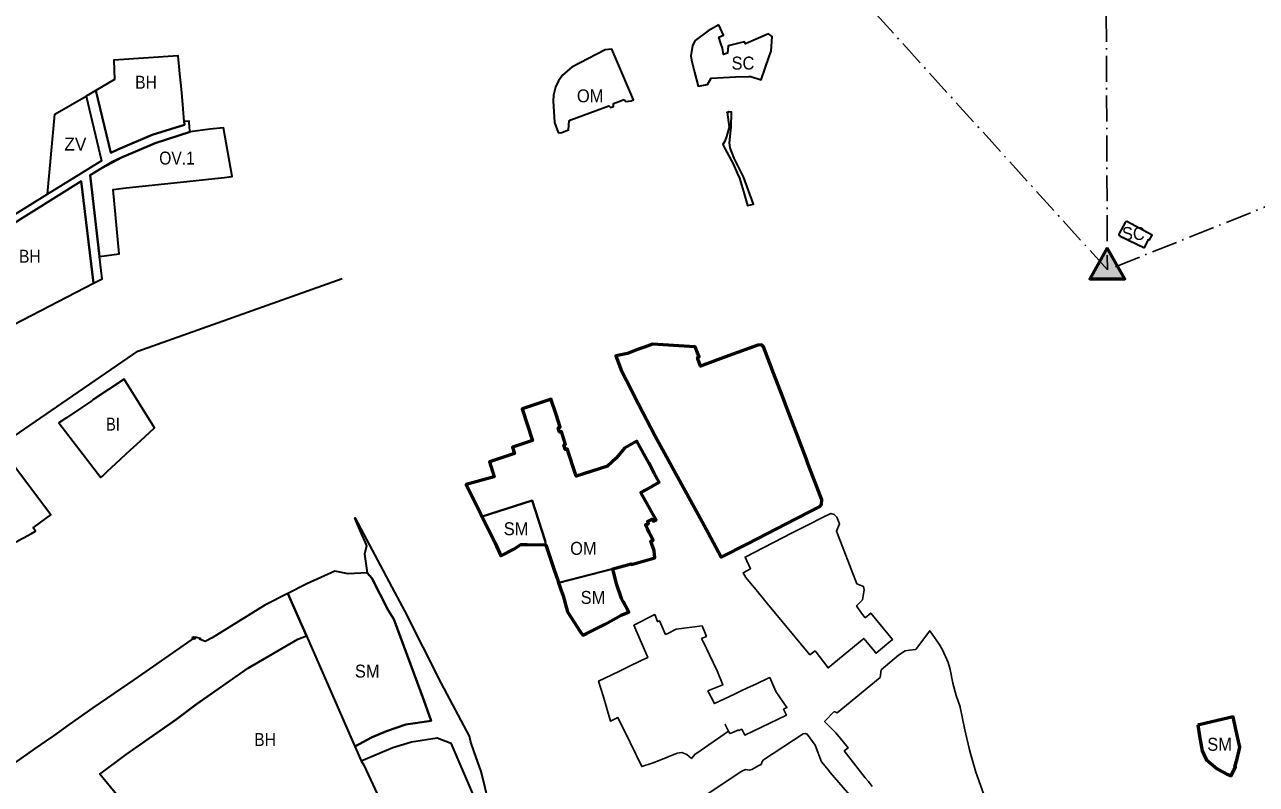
# Model space of a CAD drawing. Extents: x -650276 to -642489, y -1074311 to -1066658.
# Drawn here: x -648072 to -646929, y -1071077 to -1070373 of the extents above; entities that cross this region are included whole.
import ezdxf

# ---------------------------------------------------------------- set-up
doc = ezdxf.new("R2010")
doc.units = 0
doc.header["$LTSCALE"] = 4.8
doc.header["$PDMODE"] = 32
doc.header["$PDSIZE"] = 2.4
doc.linetypes.add('DOT_DASHED', pattern=[7.7, 5, -1.2, 0.3, -1.2])
for name, color, linetype, lineweight in [('1', 7, 'Continuous', 35), ('11', 7, 'Continuous', 35), ('12', 7, 'Continuous', 35), ('15', 7, 'Continuous', 35), ('17', 7, 'Continuous', 35), ('18', 7, 'Continuous', 35), ('2', 7, 'Continuous', 35), ('40', 7, 'Continuous', 35), ('54', 7, 'Continuous', 35), ('55', 7, 'Continuous', 53), ('60', 7, 'Continuous', 53), ('61', 7, 'Continuous', 25)]:
    doc.layers.add(name, color=color, linetype=linetype, lineweight=lineweight)
doc.layers.add('62', color=7, linetype='Continuous')

msp = doc.modelspace()

# ---------------------------------------------------------------- hatches: boundary and pattern name
at = {"layer": '55'}
msp.add_hatch(color=256, dxfattribs=at).paths.add_polyline_path([(-647067.857, -1070579.969), (-647083.808, -1070608.615), (-647051.424, -1070608.615)])

# ---------------------------------------------------------------- linework, layer by layer
at = {"layer": '1'}
for points in [[(-647991.539, -1070492.016), (-647985.19, -1070488.804), (-647953.251, -1070475.276), (-647923.247, -1070465.749), (-647923.53, -1070462.75), (-647924.63, -1070451.09), (-647925.5, -1070439.63), (-647926.53, -1070429.76), (-647927.67, -1070418.74), (-647929.24, -1070401.97), (-647988.86, -1070405.95), (-647988.11, -1070423.93), (-648005.668, -1070434.145)], [(-648098.637, -1070659.682), (-648007.838, -1070612.851), (-648019, -1070518), (-648135.47, -1070590.61), (-648105.98, -1070645.91)], [(-648001.922, -1071067.83), (-647977.41, -1071049.74), (-647930.7, -1071017.18), (-647911.838, -1071002.919), (-647864.03, -1070969.3), (-647864.03, -1070969.3), (-647818.33, -1070942.91), (-647810.243, -1070939.825), (-647759.52, -1071055.67), (-647757.19, -1071059.66), (-647742.64, -1071090.72), (-647726.74, -1071122.48), (-647742.35, -1071129.43), (-647775.982, -1071148.001), (-647775.982, -1071148.001), (-647875.939, -1071221.104)]]:
    msp.add_lwpolyline(points, close=True, dxfattribs=at)
at = {"layer": '11'}
msp.add_lwpolyline([(-647927.14, -1070519), (-647889.27, -1070514.92), (-647886.09, -1070514.58), (-647879.89, -1070513.91), (-647879.16, -1070513.83), (-647887.08, -1070468.54), (-647899.87, -1070470.04), (-647917.98, -1070472.47), (-647950.48, -1070482.79), (-647981.81, -1070496.06), (-647990.295, -1070500.352), (-647999.756, -1070505.655), (-648010.831, -1070512.588), (-648002, -1070588), (-647984.03, -1070585.46), (-647989.5, -1070525.73), (-647977.41, -1070524.43)], close=True, dxfattribs=at)
at = {"layer": '12'}
msp.add_lwpolyline([(-647515.73, -1070442.32), (-647514.23, -1070444.18), (-647509.22, -1070443.62), (-647506.95, -1070442.71), (-647522.54, -1070406.51), (-647527.1, -1070395.72), (-647533.1, -1070396.26), (-647564.01, -1070412.59), (-647572.37, -1070419.41), (-647576.48, -1070425.09), (-647579.22, -1070431.05), (-647581.04, -1070438.4), (-647581.54, -1070443.7), (-647580.1, -1070463.69), (-647576.92, -1070473), (-647574.28, -1070473.46), (-647567.32, -1070470.66), (-647566.55, -1070462.22), (-647565.11, -1070461.12), (-647529.74, -1070448.27), (-647528.28, -1070449.87), (-647525.54, -1070448.89), (-647525.45, -1070446.21)], close=True, dxfattribs=at)
msp.add_lwpolyline([(-647515.73, -1070442.32), (-647514.23, -1070444.18), (-647509.22, -1070443.62), (-647506.95, -1070442.71), (-647522.54, -1070406.51), (-647527.1, -1070395.72), (-647533.1, -1070396.26), (-647564.01, -1070412.59), (-647572.37, -1070419.41), (-647576.48, -1070425.09), (-647579.22, -1070431.05), (-647581.04, -1070438.4), (-647581.54, -1070443.7), (-647580.1, -1070463.69), (-647576.92, -1070473), (-647574.28, -1070473.46), (-647567.32, -1070470.66), (-647566.55, -1070462.22), (-647565.11, -1070461.12), (-647529.74, -1070448.27), (-647528.28, -1070449.87), (-647525.54, -1070448.89), (-647525.45, -1070446.21)], close=True, dxfattribs=at)
msp.add_lwpolyline([(-647515.73, -1070442.32), (-647514.23, -1070444.18), (-647509.22, -1070443.62), (-647506.95, -1070442.71), (-647522.54, -1070406.51), (-647527.1, -1070395.72), (-647533.1, -1070396.26), (-647564.01, -1070412.59), (-647572.37, -1070419.41), (-647576.48, -1070425.09), (-647579.22, -1070431.05), (-647581.04, -1070438.4), (-647581.54, -1070443.7), (-647580.1, -1070463.69), (-647576.92, -1070473), (-647574.28, -1070473.46), (-647567.32, -1070470.66), (-647566.55, -1070462.22), (-647565.11, -1070461.12), (-647529.74, -1070448.27), (-647528.28, -1070449.87), (-647525.54, -1070448.89), (-647525.45, -1070446.21)], close=True, dxfattribs=at)
for points in [[(-647569.92, -1070762.24), (-647573.88, -1070750.25), (-647575.58, -1070750.83), (-647576.81, -1070746.86), (-647575.09, -1070746.33), (-647578.79, -1070734.33), (-647583.38, -1070720.9), (-647583.22, -1070720.2), (-647593.6, -1070723.68), (-647610.33, -1070729.28), (-647600.53, -1070758.65), (-647619.2, -1070764.85), (-647617.36, -1070770.69)], [(-647636.12, -1070792.13), (-647654.89, -1070797.23), (-647662.26, -1070799.23), (-647650.908, -1070822.34), (-647647.405, -1070829.08), (-647609.58, -1070817.06), (-647600.8, -1070814.27), (-647588.89, -1070851.67), (-647588.4, -1070855.25), (-647584.6, -1070866.3), (-647580.22, -1070879.3), (-647578.703, -1070883.851), (-647578.703, -1070883.851), (-647576.469, -1070890.564), (-647526.13, -1070877.41), (-647509.1, -1070872.96), (-647508.96, -1070873.41), (-647487.16, -1070867.32), (-647487.91, -1070860.91), (-647490.92, -1070851.82), (-647488.8, -1070851.12), (-647494.1, -1070840.58), (-647495.93, -1070836.86), (-647493.16, -1070835.5), (-647494.03, -1070833.64), (-647489.55, -1070831.53), (-647488.75, -1070833.37), (-647485.9, -1070832), (-647500.07, -1070806.87), (-647500.07, -1070806.87), (-647483.16, -1070797.07), (-647492.81, -1070779.18), (-647492.81, -1070779.18), (-647497.227, -1070771.165), (-647503.76, -1070759.31), (-647514.49, -1070764.93), (-647517.61, -1070767.89), (-647523.07, -1070774.86), (-647531.05, -1070782.23), (-647560.06, -1070791.72), (-647566.26, -1070773.148)], [(-647570.27, -1070766.86), (-647571.63, -1070762.82), (-647569.92, -1070762.24)], [(-647566.26, -1070773.148), (-647568.55, -1070766.29), (-647570.27, -1070766.86)], [(-647617.36, -1070770.69), (-647619.12, -1070771.28), (-647640.66, -1070778.47), (-647636.12, -1070792.13)]]:
    msp.add_lwpolyline(points, dxfattribs=at)
at = {"layer": '15'}
for points in [[(-648007.838, -1070612.851), (-647999.588, -1070608.596), (-648002, -1070588), (-648010.831, -1070512.588), (-647999.756, -1070505.655), (-647981.81, -1070496.06), (-647950.48, -1070482.79), (-647917.98, -1070472.47), (-647918.54, -1070468.61), (-647918.95, -1070462.36), (-647923.53, -1070462.75), (-647923.247, -1070465.749), (-647953.251, -1070475.276), (-647985.19, -1070488.804), (-647991.539, -1070492.016), (-648005.668, -1070434.145), (-648014.63, -1070439.36), (-648000.442, -1070499.336), (-648019.789, -1070511.293), (-648050.38, -1070530.2), (-648122.57, -1070575), (-648137.78, -1070586.25), (-648135.47, -1070590.61), (-648019, -1070518)], [(-647404.96, -1070527.57), (-647401.35, -1070540.59), (-647395.75, -1070539.47), (-647404.879, -1070514.114), (-647413.552, -1070496.671), (-647417.297, -1070487.185), (-647418.038, -1070482.516), (-647417.482, -1070476.846), (-647416.37, -1070468.064), (-647416.148, -1070454.055), (-647418.49, -1070453.76), (-647420.13, -1070454.78), (-647420.22, -1070454.02), (-647418.41, -1070468.21), (-647420.74, -1070476.57), (-647422.285, -1070480.931), (-647424.226, -1070484.029), (-647422.19, -1070487.75), (-647414.6, -1070502.16), (-647410.86, -1070510.68), (-647408.82, -1070515.49)]]:
    msp.add_lwpolyline(points, close=True, dxfattribs=at)
for points in [[(-647659.01, -1071032.66), (-647685.1, -1070983.93), (-647719.06, -1070916.45), (-647728.35, -1070899.11), (-647764.84, -1070830.47), (-647765.72, -1070830.64)], [(-647765.72, -1070830.64), (-647759.08, -1070845.74), (-647755.87, -1070853.02), (-647754.6, -1070856.11), (-647756.45, -1070863.95), (-647753.81, -1070881.3)], [(-647753.81, -1070881.3), (-647749.75, -1070886.1), (-647734.48, -1070915.94), (-647729.27, -1070924.35), (-647701.45, -1070999.4)], [(-647701.45, -1070999.4), (-647694.54, -1071018.549), (-647718, -1071022), (-647736, -1071028), (-647750, -1071034), (-647765.408, -1071042.223), (-647759.52, -1071055.67), (-647730.17, -1071043.21), (-647712.74, -1071037.99), (-647688.9, -1071034.18), (-647676.96, -1071039.014)], [(-647676.96, -1071039.014), (-647676.9, -1071039.03), (-647676.45, -1071039.22), (-647656.443, -1071085.369), (-647658.55, -1071097.02), (-647669.02, -1071102.33), (-647667.35, -1071106.38), (-647655.47, -1071100.98), (-647640.727, -1071095.819)], [(-647640.727, -1071095.819), (-647648.106, -1071065.551), (-647654.747, -1071047.095), (-647657.699, -1071038.232), (-647659.01, -1071032.66)]]:
    msp.add_lwpolyline(points, dxfattribs=at)
at = {"layer": '17'}
for points in [[(-647427.8, -1070373.32), (-647437.76, -1070378.66), (-647449.69, -1070387.83), (-647452.17, -1070392.38), (-647453.71, -1070401.81), (-647453.35, -1070406.09), (-647450.51, -1070416.96), (-647446.93, -1070429.99), (-647438.45, -1070428.47), (-647434.85, -1070422.64), (-647423.38, -1070421.87), (-647412.51, -1070421.5), (-647400.41, -1070421.08), (-647398.21, -1070421.15), (-647388.6, -1070424.24), (-647381.11, -1070402.45), (-647379.3, -1070397.57), (-647378.49, -1070383.91), (-647381.65, -1070381.45), (-647400.22, -1070389.64), (-647403.27, -1070390.91), (-647404, -1070388.84), (-647409.36, -1070390.24), (-647419.08, -1070392.52), (-647419.68, -1070399.59), (-647423.58, -1070400.59), (-647424.54, -1070394.78), (-647425.99, -1070390.47), (-647427.96, -1070384.64), (-647423.57, -1070382.64)], [(-647033.01, -1070579.83), (-647029.44, -1070572.13), (-647028.52, -1070572.63), (-647026.14, -1070568.26), (-647049.52, -1070555.64), (-647050.37, -1070555.74), (-647051.14, -1070556.59), (-647052.77, -1070559.7), (-647056.79, -1070567.41), (-647056.8, -1070568.32), (-647055.79, -1070569.07)]]:
    msp.add_lwpolyline(points, close=True, dxfattribs=at)
at = {"layer": '18'}
for points in [[(-647588.4, -1070855.25), (-647588.89, -1070851.67), (-647600.8, -1070814.27), (-647609.58, -1070817.06), (-647647.405, -1070829.08)], [(-647647.405, -1070829.08), (-647635.11, -1070853.786), (-647629.92, -1070865.35), (-647618.01, -1070859.42), (-647611.3, -1070854.9), (-647605.64, -1070854.99), (-647588.4, -1070855.25)], [(-647511.37, -1070917.79), (-647516.66, -1070907.8), (-647518.12, -1070905.05), (-647522.74, -1070891.48), (-647526.13, -1070877.41), (-647576.469, -1070890.564)], [(-647576.469, -1070890.564), (-647576.43, -1070890.68), (-647575.35, -1070893.91), (-647574.09, -1070897.7), (-647572.32, -1070902.72), (-647568.2, -1070917.54), (-647556.52, -1070935.59), (-647553.94, -1070939.11)], [(-647553.94, -1070939.11), (-647553.94, -1070939.11), (-647550.59, -1070937.45), (-647533.31, -1070928.79), (-647518.35, -1070920.62)], [(-647518.35, -1070920.62), (-647514.7, -1070918.79), (-647511.37, -1070917.79)]]:
    msp.add_lwpolyline(points, dxfattribs=at)
for points in [[(-647736, -1071028), (-647718, -1071022), (-647694.54, -1071018.549), (-647701.45, -1070999.4), (-647729.27, -1070924.35), (-647734.48, -1070915.94), (-647749.75, -1070886.1), (-647753.81, -1070881.3), (-647771.47, -1070882.27), (-647783.95, -1070879.58), (-647809.74, -1070891.31), (-647827.527, -1070900.351), (-647810.243, -1070939.825), (-647765.408, -1071042.223), (-647750, -1071034)], [(-646983.66, -1071022.3), (-646982.08, -1071032.76), (-646979.75, -1071046.19), (-646976.03, -1071054.29), (-646965.69, -1071063.05), (-646956.66, -1071067.91), (-646952.75, -1071069.62), (-646948.83, -1071061.12), (-646949.48, -1071060.79), (-646947.41, -1071054.95), (-646945.38, -1071045.82), (-646944.88, -1071042.78), (-646948.89, -1071024.84), (-646949.39, -1071021.83), (-646951.06, -1071014.78), (-646955.09, -1071015.67)]]:
    msp.add_lwpolyline(points, close=True, dxfattribs=at)
at = {"layer": '2'}
for points in [[(-648032.601, -1070737.472), (-648039.82, -1070742.33), (-648000.85, -1070792.88), (-647999.06, -1070791.2), (-647994.63, -1070787.05), (-647994.63, -1070787.05), (-647982.89, -1070776.05), (-647976.97, -1070770.51), (-647964.21, -1070758.77), (-647951.11, -1070746.78), (-647979.17, -1070701.65), (-648008.28, -1070720.96), (-648009.29, -1070721.79), (-648019.49, -1070728.65)], [(-648114.77, -1070788.08), (-648125.2, -1070794.79), (-648083.65, -1070854.89), (-648076.73, -1070851.07), (-648074.41, -1070849.79), (-648072.59, -1070848.79), (-648065.35, -1070844.8), (-648061.52, -1070842.68), (-648063.76, -1070839.49), (-648056.61, -1070834.26), (-648047.17, -1070827.35), (-648089.27, -1070771.57), (-648104.78, -1070781.65)]]:
    msp.add_lwpolyline(points, close=True, dxfattribs=at)
msp.add_lwpolyline([(-647875.939, -1071221.104), (-648001.922, -1071067.83), (-647977.41, -1071049.74), (-647930.96, -1071017.383), (-647912.11, -1071003.11), (-647864.29, -1070969.503), (-647818.33, -1070942.91), (-647810.243, -1070939.825), (-647827.527, -1070900.351), (-647848.89, -1070911.21), (-647897.76, -1070941.62), (-647904.13, -1070944.78), (-647909.42, -1070942.63), (-647908.63, -1070942.1), (-647913.45, -1070940.79), (-647934.9, -1070955.87), (-647952.01, -1070967.82), (-647970.19, -1070980.45), (-647988.81, -1070993.27), (-648008.34, -1071006.32), (-648030.24, -1071021.91), (-648044.82, -1071032.25), (-648051.48, -1071036.97), (-648062.53, -1071044.59), (-648085.73, -1071060.92)], dxfattribs=at)
msp.add_point((-647914.73, -1070941.682), dxfattribs=at)
at = {"layer": '40'}
msp.add_lwpolyline([(-648014.63, -1070439.36), (-648000.442, -1070499.336), (-648050.38, -1070530.2), (-648043.43, -1070456.12)], close=True, dxfattribs=at)
at = {"layer": '54'}
msp.add_lwpolyline([(-648756.915, -1070932.76), (-648403.845, -1070737.419), (-648368.964, -1070716.905), (-648263.103, -1070807.79), (-648213.358, -1070823.563), (-648181.392, -1070823.076), (-647966.625, -1070675.686), (-647777.125, -1070608.309)], dxfattribs=at)
at = {"layer": '55', "linetype": 'DOT_DASHED', "lineweight": 25}
for p, q in [((-647072.859, -1069440.93), (-647067.564, -1070600.224)), ((-647067.564, -1070600.224), (-647577.112, -1070037.236)), ((-647060.176, -1070597.455), (-645765.418, -1070080.935))]:
    msp.add_line(p, q, dxfattribs=at)
at = {"layer": '55'}
msp.add_lwpolyline([(-647067.857, -1070579.969), (-647083.808, -1070608.615), (-647051.424, -1070608.615)], close=True, dxfattribs=at)
at = {"layer": '60'}
for points in [[(-647365.48, -1070835.85), (-647334.27, -1070819.86), (-647332.51, -1070817.97), (-647332.25, -1070813.72), (-647345.18, -1070779.89), (-647346.96, -1070775.41), (-647365.94, -1070725.08), (-647367.67, -1070720.73), (-647377.04, -1070696.22), (-647386.39, -1070671.74), (-647388.31, -1070669.95), (-647391.74, -1070670.16), (-647418.28, -1070679.89), (-647444.78, -1070689.6), (-647447.31, -1070682.72), (-647447.76, -1070681.5), (-647446.22, -1070680.91), (-647447.58, -1070677.36), (-647449.69, -1070671.81), (-647455.17, -1070671.48), (-647489.21, -1070669.41), (-647496.64, -1070671.93), (-647503.3, -1070674.3), (-647512.51, -1070677.98), (-647523.27, -1070680.11), (-647518.19, -1070693.93), (-647513.59, -1070702.8), (-647502.59, -1070724.13), (-647486.84, -1070754.54), (-647464.3, -1070795.6), (-647448.84, -1070823.79), (-647437.79, -1070844.12), (-647425.58, -1070866.7), (-647401.15, -1070854.25)], [(-647588.4, -1070855.25), (-647584.6, -1070866.3), (-647580.22, -1070879.3), (-647577.59, -1070887.19), (-647576.43, -1070890.68), (-647575.35, -1070893.91), (-647574.09, -1070897.7), (-647572.32, -1070902.72), (-647568.2, -1070917.54), (-647556.52, -1070935.59), (-647553.94, -1070939.11), (-647550.59, -1070937.45), (-647533.31, -1070928.79), (-647518.35, -1070920.62), (-647511.37, -1070917.79), (-647516.66, -1070907.8), (-647518.12, -1070905.05), (-647522.74, -1070891.48), (-647526.13, -1070877.41), (-647509.1, -1070872.96), (-647508.96, -1070873.41), (-647487.16, -1070867.32), (-647487.91, -1070860.91), (-647490.92, -1070851.82), (-647488.8, -1070851.12), (-647491.19, -1070846.49), (-647492.48, -1070843.88), (-647494.1, -1070840.58), (-647495.93, -1070836.86), (-647493.16, -1070835.5), (-647494.03, -1070833.64), (-647489.55, -1070831.53), (-647488.75, -1070833.37), (-647485.9, -1070832), (-647500.07, -1070806.87), (-647500.07, -1070806.87), (-647494.88, -1070803.86), (-647483.16, -1070797.07), (-647487.67, -1070788.86), (-647492.81, -1070779.18), (-647503.76, -1070759.31), (-647515.216, -1070765.619), (-647523.07, -1070774.86), (-647531.05, -1070782.23), (-647560.06, -1070791.72), (-647568.55, -1070766.29), (-647570.27, -1070766.86), (-647571.63, -1070762.82), (-647569.92, -1070762.24), (-647573.88, -1070750.25), (-647575.58, -1070750.83), (-647576.81, -1070746.86), (-647575.09, -1070746.33), (-647578.79, -1070734.33), (-647583.38, -1070720.9), (-647583.22, -1070720.2), (-647593.6, -1070723.68), (-647610.33, -1070729.28), (-647600.53, -1070758.65), (-647619.2, -1070764.85), (-647617.36, -1070770.69), (-647640.66, -1070778.47), (-647636.12, -1070792.13), (-647662.26, -1070799.23), (-647635.11, -1070853.786), (-647629.92, -1070865.35), (-647618.01, -1070859.42), (-647611.3, -1070854.9), (-647605.64, -1070854.99)], [(-646983.66, -1071022.3), (-646982.08, -1071032.76), (-646979.75, -1071046.19), (-646976.03, -1071054.29), (-646965.69, -1071063.05), (-646956.66, -1071067.91), (-646952.75, -1071069.62), (-646948.83, -1071061.12), (-646949.48, -1071060.79), (-646947.41, -1071054.95), (-646945.38, -1071045.82), (-646944.88, -1071042.78), (-646948.89, -1071024.84), (-646949.39, -1071021.83), (-646951.06, -1071014.78), (-646955.09, -1071015.67), (-646982.41, -1071022.23)]]:
    msp.add_lwpolyline(points, close=True, dxfattribs=at)
at = {"layer": '61'}
for points in [[(-647299.98, -1070891.49), (-647318.68, -1070842.72), (-647316.06, -1070835.75), (-647318.44, -1070829.76), (-647321.01, -1070827.14), (-647324.15, -1070826.29), (-647331.02, -1070829.74), (-647345.71, -1070837.13), (-647359.71, -1070844.27), (-647403.51, -1070866.6), (-647398.52, -1070877.49), (-647405.34, -1070881.23), (-647402.82, -1070885.66), (-647396.9, -1070892.8), (-647394.88, -1070895.23), (-647382.57, -1070910.05), (-647343.34, -1070957.27), (-647338.57, -1070953.63), (-647326.51, -1070969.42), (-647293.51, -1070942.01), (-647290.28, -1070945.89), (-647283.54, -1070954.02), (-647282.46, -1070955.31), (-647281.97, -1070955.9), (-647271.95, -1070947.47), (-647266.79, -1070942.95), (-647286.92, -1070918.59), (-647292.14, -1070922.88), (-647295.69, -1070918.55), (-647300.07, -1070911.99), (-647294.73, -1070906.32), (-647293.09, -1070897.18), (-647293.7, -1070893.99)], [(-647466.48, -1071048.33), (-647483.08, -1071055.41), (-647489.7, -1071057.66), (-647499.39, -1071060.95), (-647510.18, -1071038.65), (-647521.36, -1071015.52), (-647528.27, -1071018.94), (-647535.19, -1070995.23), (-647539.38, -1070981.6), (-647520.58, -1070972.61), (-647517.43, -1070971.1), (-647511.96, -1070968.48), (-647499.8, -1070962.67), (-647493.79, -1070959.8), (-647493.71, -1070959.89), (-647506.58, -1070929.86), (-647487.33, -1070919.95), (-647484.78, -1070926.54), (-647483.02, -1070925.66), (-647477.21, -1070938.44), (-647475.82, -1070937.77), (-647467.47, -1070933.53), (-647443.36, -1070930.41), (-647439.33, -1070940.28), (-647443.84, -1070942.26), (-647442.33, -1070945.38), (-647441.9, -1070946.28), (-647436.58, -1070957.29), (-647429.44, -1070972.06), (-647424.16, -1070985.19), (-647438.05, -1070990.74), (-647431.74, -1071002.56), (-647413.35, -1070993.67), (-647410.26, -1070992.23), (-647407.22, -1070990.81), (-647401.93, -1070988.34), (-647392.83, -1070984.14), (-647382.05, -1070979.01), (-647380.69, -1070978.37), (-647374.95, -1070991.15), (-647364.66, -1071006.25), (-647367.88, -1071007.78), (-647365.21, -1071013.19), (-647403.85, -1071031.66), (-647406.65, -1071026.24), (-647409.36, -1071027.52), (-647409.68, -1071026.85), (-647411.52, -1071027.64), (-647415.84, -1071029.49), (-647417.76, -1071030.31), (-647418.88, -1071028.01), (-647421.89, -1071021.82), (-647418.88, -1071028.01), (-647448.32, -1071048.39), (-647449.88, -1071049.31), (-647453.32, -1071053.37), (-647457.4, -1071049.84), (-647462.03, -1071047.83)]]:
    msp.add_lwpolyline(points, close=True, dxfattribs=at)
for points in [[(-647285.53, -1071079.39), (-647289.1, -1071074.88), (-647292.21, -1071071.21), (-647298.74, -1071062.85), (-647311.58, -1071046.44), (-647308, -1071043.56), (-647319.46, -1071029.7), (-647329.84, -1071018.95), (-647320.83, -1071009.87), (-647317.99, -1071010.98), (-647278.2, -1070978.19), (-647277.18, -1070971.26), (-647261.35, -1070957.45), (-647255.21, -1070953.46), (-647251.11, -1070953.01), (-647245.32, -1070952.38), (-647237.16, -1070941.5), (-647232.24, -1070934.94), (-647223.65, -1070947.55), (-647220.46, -1070952.68), (-647215.29, -1070964.36), (-647213.23, -1070970.92), (-647210.97, -1070983.56), (-647207.77, -1070995.03), (-647204.055, -1071005.609), (-647203.96, -1071005.88), (-647199.63, -1071026.94), (-647195.64, -1071044.04), (-647194.61, -1071048.68), (-647192.72, -1071055.27), (-647189.68, -1071065.99), (-647181.99, -1071086.74)], [(-647442.36, -1071088.82), (-647406.52, -1071065.05), (-647403.15, -1071063.6), (-647399.31, -1071064.09), (-647397.17, -1071063.56), (-647390.72, -1071059.94), (-647388.51, -1071058.82), (-647387.82, -1071056.14), (-647386.3, -1071054.58), (-647349.67, -1071030.64), (-647347.66, -1071030.16), (-647345.94, -1071030.88), (-647338.47, -1071040.94), (-647332.55, -1071056.58), (-647326.18, -1071064.18), (-647324.46, -1071066.41), (-647290.44, -1071106.08)]]:
    msp.add_lwpolyline(points, dxfattribs=at)

# ---------------------------------------------------------------- texts
at = {"layer": '62'}
for s, width, p in [('SC', 0.95, (-647416.06, -1070414.645)), ('BH', 0.9, (-647969.069, -1070432.39)), ('OM', 0.95, (-647559.43, -1070445.015)), ('OV.1', 0.9, (-647946.769, -1070502.709)), ('SC', 0.95, (-647054.06, -1070572.645)), ('BH', 0.9, (-648076.769, -1070593.709)), ('BI', 0.85, (-647996.127, -1070749.398)), ('SM', 0.95, (-647627.328, -1070846.374)), ('OM', 0.95, (-647565.708, -1070864.552)), ('SM', 0.95, (-647556.006, -1070910.054)), ('SM', 0.95, (-647765.328, -1070978.374)), ('BH', 0.9, (-647858.64, -1071041.819)), ('SM', 0.95, (-646974.938, -1071046.245))]:
    msp.add_text(s, height=12, dxfattribs=dict(at, width=width)).set_placement(p)
msp.add_text('ZV', height=12, dxfattribs=at).set_placement((-648034.769, -1070489.709))

doc.saveas('drawing.dxf')
